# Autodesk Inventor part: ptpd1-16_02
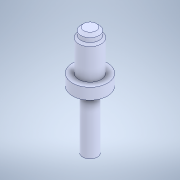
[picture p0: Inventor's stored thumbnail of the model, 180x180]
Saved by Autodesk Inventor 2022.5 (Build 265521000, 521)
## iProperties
Created: 2023-04
Part Number: ptpd1-16_02
Material: Generic
Document SubType Name: Modeling
Designer: ImaoCorp
Density: 1 g/cm^3
Appearance: Default
Author: ImaoCorp
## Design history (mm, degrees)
feature "ptpd1-16_02"
node "ソリッド1"
